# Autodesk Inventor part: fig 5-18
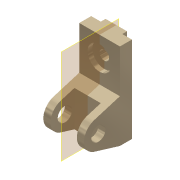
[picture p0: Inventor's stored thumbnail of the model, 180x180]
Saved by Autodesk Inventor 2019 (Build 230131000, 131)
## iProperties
Shininess: 65.0
Angle Display Precision: 2
Document Length Units: 11269
Document Angle Units: 11279
Document Time Units: 11290
Document Mass Units: 11283
Document Length Units Precision: 3
Document Angle Units Precision: 2
Compacted: False
Created: 2001-11
Part Number: fig 5-18
Document SubType Name: Modeling
Designer: Renu Muthoo
Density: 1 g/cm^3
Material: Generic
Appearance: Metal-Titanium (Polished)
Density: 0.0
Volumn: 0.0
Area: 0.0
PropertySet Name: Model Information
Control State: 0
Master: False
Checked Out: False
Author: Renu Muthoo
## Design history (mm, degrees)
node "Sketch1"
sketch "Sketch2"
  geometry: L1 (33.257, 104.664)-(33.257, -75.336); L2 (33.257, -75.336)-(8.257, -75.336); L3 (8.257, -75.336)-(-45.451, -59.045); L4 (-45.451, -1.628)-(8.257, 14.664); L5 (8.257, 14.664)-(8.257, 104.664); L6 (8.257, 104.664)-(33.257, 104.664); C1 r 15 at (-36.743, -30.336); A1 r 30 centre (-36.743, -30.336) between (-45.451, -1.628) and (-45.451, -59.045)
  constraints: 12 end point, 2 centre point, 2 equal length, 2 parallel, 2 point on circle, 2 tangent, 1 coincident, 1 perpendicular, 1 vertical
  dimensions: "d0" = 180 distance of L1.start L1.end; "d1" = 30 radius of A1; "d2" = 25 distance of L5.end L1.start; "d3" = 45 distance from line of L2 A1.centre; "d4" = 70 distance from line of L1 A1.centre; "d5" = 30 diameter of C1
extrude "Extrusion1" new body sketch "Sketch2" distance "d6" = 85; taper "d7" = 0 deg
workplane "Work Plane1"
sketch "Sketch3"
  geometry: L1 (15, 62.364)-(70, 62.364); L2 (70, 62.364)-(70, -52.386); L3 (70, -52.386)-(15, -52.386); L4 (15, -52.386)-(15, 62.364); L5 (0, -45)-(0, -28.708) reference
  constraints: 8 end point, 2 parallel, 1 horizontal, 1 perpendicular
  dimensions: "d8" = 55 distance of L1.start L1.end; "d9" = 15 distance between parallel lines of L5 L4
extrude "Extrusion2" cut sketch "Sketch3" distance "d10" = 50; taper "d11" = 0 deg
sketch "Sketch4"
  geometry: L1 (0, 25)-(85, 25) reference; L2 (0, 0)-(0, 25) reference; L3 (20, 25)-(65, 25); L4 (65, 25)-(65, 35); L5 (65, 35)-(20, 35); L6 (20, 35)-(20, 25)
  constraints: 8 end point, 2 parallel, 1 horizontal, 1 perpendicular, 1 point on line
  dimensions: "d12" = 45 distance of L4.end L5.end; "d13" = 10 distance of L3.end L4.end; "d14" = 20 distance between parallel lines of L2 L6
extrude "Extrusion3" join sketch "Sketch4" stored distance "d15" = 50; taper "d16" = 0 deg
sketch "Sketch5"
  geometry: L1 (85, 0)-(85, 90) reference; L2 (0, 90)-(85, 90) reference; 1 further point
  dimensions: "d17" = 42 distance from line of L2 point (42.5, 48); "d18" = 42.5 distance from line of L1 point (42.5, 48)
hole "Hole1" sketch "Sketch5" at (42.5, 48) diameter "d19" = 20; stored, may be unused: countersink angle "d23" = 82 deg, drill point angle "d25" = 118 deg; dims "d20" = 6, "d21" = 50, "d22" = 10, "d24" = 8
workplane "Work Plane9"
body "Solid1"
